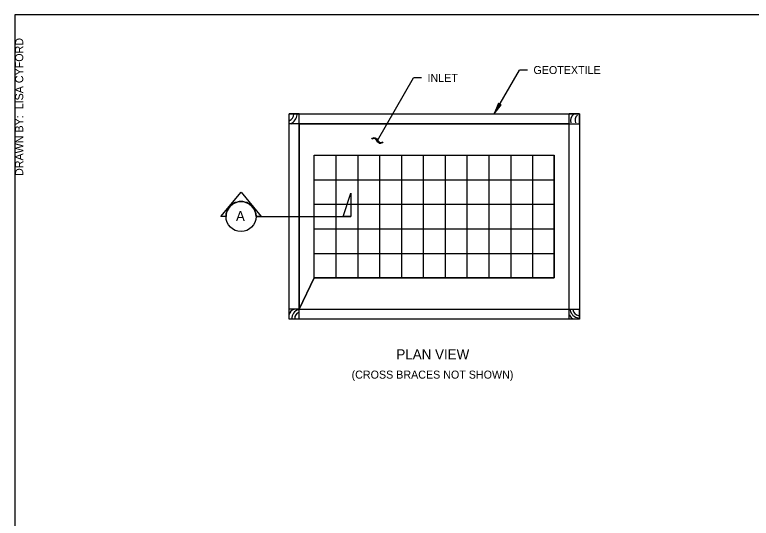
# Model space of a CAD drawing. Extents: x 99862 to 103151, y 100000 to 102076.
# Drawn here: x 99862 to 101334, y 101069 to 102076 of the extents above; entities that cross this region are included whole.
import ezdxf

# ---------------------------------------------------------------- set-up
doc = ezdxf.new("R2010")
doc.units = 0
for name, color, linetype in [('Level 1', 7, 'Continuous'), ('Level 10', 7, 'Continuous'), ('Level 11', 7, 'Continuous'), ('Level 15', 7, 'Continuous'), ('Level 2', 7, 'Continuous'), ('Level 20', 7, 'Continuous'), ('Level 62', 7, 'Continuous'), ('Level 9', 7, 'Continuous')]:
    doc.layers.add(name, color=color, linetype=linetype)

msp = doc.modelspace()

# ---------------------------------------------------------------- linework, layer by layer
at = {"layer": 'Level 1'}
msp.add_lwpolyline([(99862, 99999.5), (103151, 99999.5), (103151, 102075.5), (99862, 102075.5)], close=True, dxfattribs=at)
at = {"layer": 'Level 10'}
for p, q in [((100460.3, 101794.7), (100940.3, 101794.7)), ((100460.3, 101549.7), (100460.3, 101794.7)), ((100504, 101794.7), (100504, 101549.7)), ((100547.6, 101794.7), (100547.6, 101549.7)), ((100591.2, 101794.7), (100591.2, 101549.7)), ((100634.9, 101794.7), (100634.9, 101549.7)), ((100678.5, 101794.7), (100678.5, 101549.7)), ((100722.1, 101794.7), (100722.1, 101549.7)), ((100765.8, 101794.7), (100765.8, 101549.7)), ((100809.4, 101794.7), (100809.4, 101549.7)), ((100853.1, 101794.7), (100853.1, 101549.7)), ((100896.7, 101794.7), (100896.7, 101549.7)), ((100940.3, 101549.7), (100940.3, 101794.7)), ((100460.3, 101745.7), (100940.3, 101745.7)), ((100460.3, 101696.7), (100940.3, 101696.7)), ((100460.3, 101647.7), (100940.3, 101647.7)), ((100460.3, 101598.7), (100940.3, 101598.7)), ((100460.3, 101549.7), (100940.3, 101549.7))]:
    msp.add_line(p, q, dxfattribs=at)
at = {"layer": 'Level 11'}
for p, q in [((100410.3, 101467.2), (100410.3, 101877.2)), ((100410.3, 101877.2), (100990.3, 101877.2)), ((100990.3, 101877.2), (100990.3, 101467.2)), ((100990.3, 101467.2), (100410.3, 101467.2))]:
    msp.add_line(p, q, dxfattribs=at)
at = {"layer": 'Level 15'}
for p, q in [((100819.9, 101877.2), (100870.6, 101965)), ((100886.6, 101965), (100870.6, 101965)), ((100586.7, 101824.1), (100658.9, 101949.3)), ((100674.9, 101949.3), (100658.9, 101949.3)), ((100575.8, 101827.1), (100576.8, 101828.9)), ((100579.3, 101828), (100575.8, 101827.1)), ((100576.8, 101828.9), (100578.8, 101829.7)), ((100578.8, 101829.7), (100580.6, 101829.9)), ((100581, 101828), (100579.3, 101828)), ((100580.6, 101829.9), (100582.2, 101829.8)), ((100582.3, 101827.5), (100581, 101828)), ((100582.2, 101829.8), (100583.7, 101829.1)), ((100583.5, 101826.5), (100582.3, 101827.5)), ((100584.9, 101824.6), (100583.5, 101826.5)), ((100583.7, 101829.1), (100585.7, 101827.6)), ((100585.7, 101827.6), (100587.9, 101824.2)), ((100587.4, 101820.9), (100584.9, 101824.6)), ((100589.5, 101819.2), (100587.4, 101820.9)), ((100587.9, 101824.2), (100589.4, 101822.1)), ((100589.4, 101822.1), (100590.9, 101820.8)), ((100591.1, 101818.5), (100589.5, 101819.2)), ((100590.9, 101820.8), (100592.1, 101820.3)), ((100592.8, 101818.3), (100591.1, 101818.5)), ((100592.1, 101820.3), (100593.4, 101820.2)), ((100594.6, 101818.6), (100592.8, 101818.3)), ((100593.4, 101820.2), (100595.2, 101820.5)), ((100596.4, 101819.4), (100594.6, 101818.6)), ((100595.2, 101820.5), (100597.5, 101821.2)), ((100597.5, 101821.2), (100596.4, 101819.4))]:
    msp.add_line(p, q, dxfattribs=at)
msp.add_lwpolyline([(100819.9, 101877.2), (100833.9, 101895.5), (100830.8, 101896.1), (100828.7, 101898.5)], close=True, dxfattribs=at)
at = {"layer": 'Level 2'}
for p, q in [((100430.3, 101487.2), (100430.3, 101857.2)), ((100430.3, 101857.2), (100970.3, 101857.2)), ((100970.3, 101487.2), (100970.3, 101857.2)), ((100430.3, 101487.2), (100970.3, 101487.2))]:
    msp.add_line(p, q, dxfattribs=at)
msp.add_lwpolyline([(100460.3, 101794.7), (100940.3, 101794.7), (100940.3, 101549.7), (100460.3, 101549.7), (100430.3, 101487.2), (100970.3, 101487.2), (100970.3, 101857.2), (100430.3, 101857.2), (100430.3, 101487.2), (100460.3, 101549.7)], close=True, dxfattribs=at)
at = {"layer": 'Level 20'}
msp.add_lwpolyline([(100344.2, 101672.4), (100533.9, 101672.4)], dxfattribs=at)
at = {"layer": 'Level 9'}
for p, q in [((100430.3, 101877.2), (100410.3, 101877.2)), ((100410.3, 101857.2), (100410.3, 101877.2)), ((100430.3, 101857.2), (100430.3, 101877.2)), ((100970.3, 101857.2), (100970.3, 101877.2)), ((100990.3, 101877.2), (100970.3, 101877.2)), ((100990.3, 101857.2), (100990.3, 101877.2)), ((100430.3, 101857.2), (100410.3, 101857.2)), ((100970.3, 101857.2), (100990.3, 101857.2)), ((100273.6, 101672.3), (100314.2, 101720.8)), ((100314.2, 101720.8), (100354.8, 101672.3)), ((100284.2, 101672.3), (100273.6, 101672.3)), ((100354.8, 101672.3), (100344.2, 101672.3)), ((100430.3, 101487.2), (100410.3, 101487.2)), ((100410.3, 101467.2), (100410.3, 101487.2)), ((100430.3, 101467.2), (100430.3, 101487.2)), ((100970.3, 101487.2), (100990.3, 101487.2)), ((100970.3, 101467.2), (100970.3, 101487.2)), ((100990.3, 101467.2), (100990.3, 101487.2)), ((100430.3, 101467.2), (100410.3, 101467.2)), ((100990.3, 101467.2), (100970.3, 101467.2))]:
    msp.add_line(p, q, dxfattribs=at)
msp.add_lwpolyline([(100518.3, 101672.3), (100533.9, 101719.2), (100533.9, 101672.3)], close=True, dxfattribs=at)
msp.add_circle((100314.2, 101672.3), 30, dxfattribs=at)
for centre, radius, start, end in [((100402.6, 101879), 17.4, 297.8556, 352.0834), ((100402.6, 101879), 24, 297.8556, 352.0834), ((100988.2, 101863.6), 15.7, 123.8405, 196.3749), ((100995.1, 101864.4), 13.4, 130.7785, 202.7564), ((100314.2, 101672.3), 30, 359.9978, 180.0022), ((100423.3, 101474.3), 13, 106.1818, 170.1631), ((100432.5, 101469.8), 16.5, 102.4222, 188.1383), ((100432.5, 101469.8), 11, 102.4222, 188.1383), ((100980.5, 101476.7), 9.12, 184.491, 248.7873), ((100991.5, 101489.2), 20, 191.8882, 260.0406), ((100991.5, 101489.2), 14.7, 191.8882, 260.0406)]:
    msp.add_arc(centre, radius, start, end, dxfattribs=at)

# ---------------------------------------------------------------- texts
at = {"layer": 'Level 20'}
for s, p in [('GEOTEXTILE', (100898.6, 101957)), ('INLET', (100686.9, 101941.3))]:
    msp.add_text(s, height=16, rotation=360, dxfattribs=at).set_placement(p)
for s, height, p in [('A', 20, (100304.1, 101663.2)), ('PLAN VIEW', 20, (100624.7, 101387)), ('(CROSS BRACES NOT SHOWN)', 16, (100535.2, 101348.4))]:
    msp.add_text(s, height=height, dxfattribs=at).set_placement(p)
at = {"layer": 'Level 62'}
msp.add_text('DRAWN BY:  LISA CYFORD', height=16, rotation=90, dxfattribs=at).set_placement((99879, 101753.3))

doc.saveas('drawing.dxf')
